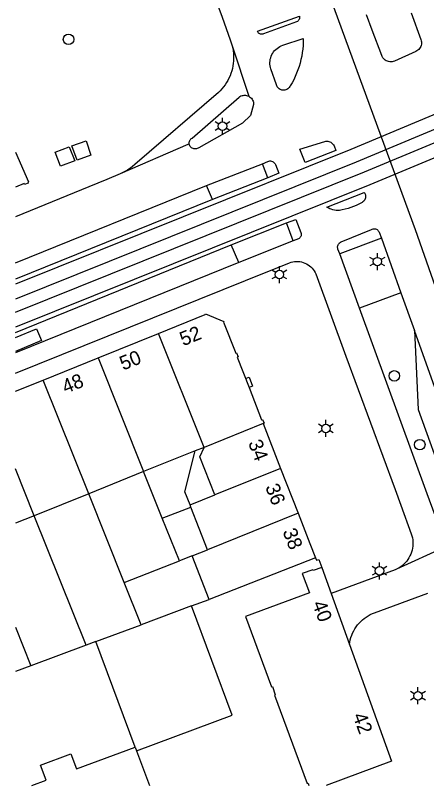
# Model space of a CAD drawing. Extents: x 122462 to 123306, y 485548 to 486417.
# Drawn here: x 122462 to 122505.6, y 485548.3 to 485629.9 of the extents above; entities that cross this region are included whole.
import ezdxf

# ---------------------------------------------------------------- set-up
doc = ezdxf.new("R2010")
doc.units = 0
for name, color, linetype in [('Level 1', 7, 'Continuous'), ('Level 17', 7, 'Continuous'), ('Level 18', 7, 'Continuous'), ('Level 19', 7, 'Continuous'), ('Level 37', 7, 'Continuous'), ('Level 4', 7, 'Continuous'), ('Level 40', 7, 'Continuous'), ('Level 42', 7, 'Continuous'), ('Level 44', 7, 'Continuous'), ('Level 50', 7, 'Continuous'), ('Level 53', 7, 'Continuous'), ('Level 58', 7, 'Continuous')]:
    doc.layers.add(name, color=color, linetype=linetype)

msp = doc.modelspace()

# ---------------------------------------------------------------- linework, layer by layer
at = {"layer": 'Level 1'}
for p, q in [((122470.791, 485593.618), (122477.188, 485596.206)), ((122464.972, 485591.263), (122470.791, 485593.618)), ((122462.03, 485590.085), (122464.972, 485591.263)), ((122488.303, 485586.662), (122490.155, 485581.91)), ((122481.105, 485583.771), (122475.629, 485581.571)), ((122482.032, 485584.143), (122481.105, 485583.771)), ((122475.629, 485581.571), (122469.807, 485579.232)), ((122490.155, 485581.91), (122492.007, 485577.158)), ((122469.807, 485579.232), (122464.019, 485576.907)), ((122480.559, 485578.056), (122483.173, 485579.106)), ((122480.65, 485577.824), (122480.559, 485578.056)), ((122482.412, 485573.304), (122480.65, 485577.824)), ((122464.019, 485576.907), (122462.03, 485576.108)), ((122480.769, 485572.644), (122482.412, 485573.304)), ((122482.568, 485568.031), (122480.769, 485572.644)), ((122494.511, 485571.416), (122495.507, 485568.664)), ((122495.507, 485568.664), (122497.456, 485563.281)), ((122480.716, 485567.344), (122482.568, 485568.031)), ((122474.726, 485552.407), (122474.878, 485551.999))]:
    msp.add_line(p, q, dxfattribs=at)
for points in [[(122462.03, 485615.407), (122463.422, 485612.251), (122463.356, 485612.224), (122463.397, 485612.117), (122463.005, 485611.965), (122462.966, 485612.068), (122462.03, 485611.693)], [(122477.188, 485596.206), (122482.171, 485598.221), (122482.199, 485598.289), (122484.13, 485597.461), (122484.102, 485597.392), (122485.398, 485594.104), (122485.489, 485594.14), (122485.651, 485593.726), (122485.559, 485593.69), (122486.808, 485590.49)], [(122486.808, 485590.49), (122488.143, 485587.071), (122488.234, 485587.107), (122488.393, 485586.695), (122488.303, 485586.662)], [(122483.173, 485579.106), (122481.6, 485583.14), (122482.032, 485584.143)], [(122492.007, 485577.158), (122493.248, 485573.974), (122493.85, 485572.428)], [(122493.85, 485572.428), (122493.947, 485572.179), (122494.199, 485572.269), (122494.511, 485571.416)], [(122474.878, 485551.999), (122485.001, 485555.779), (122480.716, 485567.344)], [(122497.456, 485563.281), (122501.929, 485550.92), (122494.98, 485548.322)], [(122463.787, 485548.322), (122465.293, 485548.884), (122464.695, 485550.486), (122467.91, 485551.687), (122468.508, 485550.086), (122474.726, 485552.407)]]:
    msp.add_lwpolyline(points, dxfattribs=at)
at = {"layer": 'Level 17'}
for p, q in [((122485.014, 485626.68), (122486.767, 485621.327)), ((122482.281, 485611.861), (122488.231, 485614.151)), ((122488.811, 485612.681), (122488.231, 485614.151)), ((122488.811, 485612.681), (122482.941, 485610.391)), ((122462.03, 485603.685), (122482.281, 485611.861)), ((122482.941, 485610.391), (122482.281, 485611.861)), ((122484.91, 485605.599), (122490.78, 485607.929)), ((122491.47, 485606.009), (122490.78, 485607.929)), ((122491.47, 485606.009), (122485.71, 485603.709)), ((122500.84, 485606.279), (122496.43, 485604.619)), ((122500.84, 485606.279), (122502.91, 485600.499)), ((122485.71, 485603.709), (122484.91, 485605.599)), ((122498.51, 485598.889), (122496.43, 485604.619)), ((122485.71, 485603.709), (122462.03, 485594.152)), ((122502.91, 485600.499), (122498.51, 485598.889)), ((122502.91, 485600.499), (122504.34, 485596.519)), ((122507.738, 485573.663), (122502.435, 485571.247))]:
    msp.add_line(p, q, dxfattribs=at)
for points in [[(122483.504, 485630.951), (122483.947, 485629.713), (122484.814, 485627.292), (122485.014, 485626.68)], [(122503.986, 485630.163), (122505.038, 485627.323), (122505.074, 485627.202), (122505.095, 485627.078), (122505.1, 485626.952), (122505.089, 485626.826), (122505.063, 485626.703), (122505.021, 485626.584), (122504.965, 485626.471), (122504.895, 485626.367), (122504.812, 485626.271), (122504.718, 485626.187), (122504.614, 485626.116), (122504.502, 485626.058), (122502.215, 485625.056), (122502.097, 485625.013), (122501.974, 485624.985), (122501.849, 485624.972), (122501.723, 485624.976), (122501.598, 485624.995), (122501.477, 485625.03), (122501.362, 485625.08), (122501.253, 485625.144), (122501.153, 485625.221), (122501.064, 485625.31), (122500.987, 485625.409), (122500.923, 485625.517), (122500.873, 485625.633), (122499.868, 485628.312), (122499.266, 485629.949)], [(122488.118, 485627.891), (122488.037, 485627.901), (122487.96, 485627.926), (122487.889, 485627.965), (122487.826, 485628.016), (122487.773, 485628.078), (122487.733, 485628.149), (122487.707, 485628.226), (122492.155, 485629.821), (122492.168, 485629.729), (122492.165, 485629.636), (122492.146, 485629.545), (122492.112, 485629.458), (122492.064, 485629.378), (122492.003, 485629.308), (122491.932, 485629.248), (122491.851, 485629.202), (122488.329, 485627.938), (122488.266, 485627.911), (122488.199, 485627.896), (122488.118, 485627.891)], [(122490.508, 485621.965), (122490.403, 485621.965), (122490.3, 485621.98), (122490.199, 485622.008), (122490.103, 485622.05), (122490.014, 485622.105), (122489.933, 485622.171), (122489.861, 485622.247), (122489.801, 485622.333), (122489.752, 485622.426), (122489.717, 485622.524), (122489.115, 485624.215), (122489.069, 485624.382), (122489.037, 485624.552), (122489.02, 485624.724), (122489.018, 485624.897), (122489.031, 485625.07), (122489.059, 485625.241), (122489.102, 485625.408), (122489.159, 485625.572), (122489.23, 485625.73), (122489.314, 485625.881), (122489.411, 485626.024), (122489.521, 485626.158), (122489.641, 485626.282), (122489.772, 485626.396), (122489.912, 485626.497), (122490.061, 485626.586), (122490.216, 485626.662), (122490.378, 485626.724), (122492.546, 485627.451), (122492.545, 485627.073), (122492.529, 485626.696), (122492.497, 485626.32), (122492.45, 485625.945), (122492.388, 485625.572), (122492.311, 485625.203), (122492.219, 485624.836), (122492.112, 485624.474), (122491.991, 485624.117), (122491.855, 485623.764), (122491.705, 485623.417), (122491.541, 485623.077), (122491.364, 485622.744), (122491.173, 485622.418), (122491.13, 485622.349), (122491.069, 485622.259), (122490.996, 485622.179), (122490.912, 485622.109), (122490.82, 485622.052), (122490.72, 485622.008), (122490.616, 485621.979), (122490.508, 485621.965)], [(122485.014, 485626.68), (122485.075, 485626.416), (122485.121, 485626.148), (122485.153, 485625.879), (122485.171, 485625.608), (122485.173, 485625.336), (122485.162, 485625.065), (122485.135, 485624.795), (122485.094, 485624.527), (122485.039, 485624.261), (122484.969, 485623.999), (122484.886, 485623.741), (122484.789, 485623.487), (122484.678, 485623.24), (122484.554, 485622.998), (122484.417, 485622.764), (122484.268, 485622.537), (122484.107, 485622.319), (122483.934, 485622.109), (122483.75, 485621.91), (122483.556, 485621.72), (122474.703, 485614.082), (122474.465, 485613.891), (122474.219, 485613.712), (122473.964, 485613.545), (122473.702, 485613.39), (122473.432, 485613.249), (122473.156, 485613.12)], [(122480.474, 485616.266), (122480.465, 485616.358), (122480.471, 485616.45), (122480.489, 485616.54), (122480.521, 485616.626), (122480.565, 485616.707), (122480.621, 485616.781), (122480.686, 485616.845), (122480.761, 485616.899), (122485.746, 485621.228), (122485.845, 485621.296), (122485.952, 485621.351), (122486.065, 485621.392), (122486.182, 485621.419), (122486.302, 485621.43), (122486.422, 485621.427), (122486.541, 485621.408), (122486.657, 485621.375), (122486.767, 485621.327)], [(122486.767, 485621.327), (122486.87, 485621.266), (122486.965, 485621.192), (122487.05, 485621.107), (122487.124, 485621.012), (122487.185, 485620.909), (122487.233, 485620.798), (122487.266, 485620.683), (122487.285, 485620.564), (122487.288, 485620.444), (122486.96, 485619.298), (122486.118, 485618.462), (122481.468, 485615.877), (122481.395, 485615.828), (122481.315, 485615.791), (122481.231, 485615.764), (122481.144, 485615.75), (122481.051, 485615.748), (122480.959, 485615.761), (122480.87, 485615.787), (122480.785, 485615.826), (122480.708, 485615.877), (122480.639, 485615.939), (122480.58, 485616.01), (122480.532, 485616.09), (122480.496, 485616.176), (122480.474, 485616.266)], [(122492.752, 485614.311), (122492.184, 485615.734), (122494.832, 485616.542), (122494.938, 485616.564), (122495.046, 485616.573), (122495.155, 485616.567), (122495.262, 485616.547), (122495.365, 485616.513), (122495.463, 485616.466), (122495.553, 485616.406), (122495.635, 485616.335), (122495.708, 485616.254), (122495.768, 485616.164), (122495.817, 485616.067), (122495.997, 485615.596), (122492.752, 485614.311)], [(122480.474, 485616.266), (122480.323, 485616.201), (122473.156, 485613.12)], [(122488.231, 485614.151), (122488.807, 485614.419), (122488.899, 485614.451), (122488.996, 485614.468), (122489.093, 485614.469), (122489.19, 485614.454), (122489.283, 485614.424), (122489.37, 485614.379), (122489.448, 485614.32), (122489.515, 485614.249), (122489.571, 485614.169), (122489.612, 485614.08), (122489.951, 485613.171), (122488.811, 485612.681)], [(122473.156, 485613.12), (122471.723, 485612.514), (122469.801, 485611.721), (122462.03, 485608.571)], [(122496.214, 485609.231), (122496.037, 485609.238), (122495.862, 485609.261), (122495.69, 485609.298), (122495.521, 485609.35), (122495.357, 485609.416), (122495.2, 485609.496), (122495.05, 485609.589), (122499.01, 485611.139), (122499.069, 485611.055), (122499.115, 485610.964), (122499.147, 485610.867), (122499.164, 485610.766), (122499.167, 485610.664), (122499.154, 485610.562), (122499.126, 485610.464), (122499.084, 485610.371), (122499.029, 485610.284), (122498.962, 485610.207), (122498.884, 485610.141), (122498.797, 485610.087), (122498.456, 485609.908), (122498.177, 485609.77), (122497.891, 485609.646), (122497.599, 485609.535), (122497.303, 485609.439), (122497.002, 485609.358), (122496.697, 485609.291), (122496.39, 485609.239), (122496.214, 485609.231)], [(122482.941, 485610.391), (122462.03, 485601.943)], [(122490.78, 485607.929), (122491.76, 485608.279), (122492.314, 485606.884), (122492.339, 485606.801), (122492.349, 485606.714), (122492.345, 485606.627), (122492.325, 485606.543), (122492.29, 485606.463), (122492.243, 485606.39), (122492.183, 485606.326), (122492.114, 485606.274), (122492.036, 485606.235), (122491.47, 485606.009)], [(122496.43, 485604.619), (122496.235, 485605.136), (122496.209, 485605.225), (122496.197, 485605.317), (122496.199, 485605.409), (122496.216, 485605.5), (122496.246, 485605.588), (122496.289, 485605.67), (122496.345, 485605.744), (122496.411, 485605.809), (122496.486, 485605.862), (122496.569, 485605.904), (122499.79, 485607.219), (122499.87, 485607.258), (122499.955, 485607.284), (122500.044, 485607.296), (122500.133, 485607.294), (122500.22, 485607.278), (122500.304, 485607.248), (122500.382, 485607.205), (122500.453, 485607.15), (122500.513, 485607.085), (122500.563, 485607.011), (122500.6, 485606.93), (122500.84, 485606.279)], [(122462.03, 485596.32), (122484.91, 485605.599)], [(122462.03, 485591.998), (122486.445, 485601.812), (122491.081, 485603.675), (122491.258, 485603.736), (122491.44, 485603.782), (122491.625, 485603.812), (122491.812, 485603.826), (122492, 485603.824), (122492.186, 485603.806), (122492.371, 485603.773), (122492.552, 485603.724), (122492.728, 485603.659), (122492.898, 485603.58), (122493.061, 485603.487), (122493.215, 485603.38), (122493.359, 485603.26), (122493.493, 485603.128), (122493.615, 485602.986), (122493.724, 485602.834), (122493.82, 485602.673), (122493.902, 485602.504), (122497.08, 485593.799), (122502.289, 485579.69), (122502.894, 485578.034), (122504.014, 485574.968), (122504.077, 485574.761), (122504.125, 485574.549), (122504.158, 485574.335), (122504.176, 485574.119), (122504.178, 485573.902), (122504.164, 485573.685), (122504.135, 485573.471), (122504.091, 485573.258), (122504.032, 485573.05), (122503.958, 485572.846), (122503.869, 485572.648), (122503.767, 485572.457), (122503.651, 485572.274), (122503.522, 485572.099), (122503.381, 485571.934), (122503.229, 485571.78), (122503.066, 485571.637), (122502.894, 485571.505), (122502.712, 485571.387), (122502.435, 485571.247)], [(122507.738, 485573.663), (122505.706, 485579.217), (122498.51, 485598.889)], [(122521.644, 485548.322), (122509.916, 485580.988), (122504.34, 485596.519)], [(122504.34, 485596.519), (122504.742, 485588.142), (122507.678, 485580.047), (122509.348, 485575.418), (122509.376, 485575.322), (122509.392, 485575.223), (122509.395, 485575.123), (122509.386, 485575.024), (122509.364, 485574.926), (122509.331, 485574.832), (122509.095, 485574.31), (122509.038, 485574.218), (122508.969, 485574.135), (122508.888, 485574.063), (122508.797, 485574.004), (122508.699, 485573.959), (122507.738, 485573.663)], [(122502.435, 485571.247), (122502.292, 485571.185), (122495.507, 485568.664)], [(122497.456, 485563.281), (122497.493, 485563.528), (122497.545, 485563.773), (122497.612, 485564.013), (122497.694, 485564.249), (122497.79, 485564.48), (122497.9, 485564.704), (122498.023, 485564.922), (122498.16, 485565.131), (122498.31, 485565.331), (122498.471, 485565.522), (122498.644, 485565.702), (122498.827, 485565.872), (122499.021, 485566.029), (122499.224, 485566.175), (122499.436, 485566.308), (122499.655, 485566.427), (122499.882, 485566.533), (122500.114, 485566.625), (122505.771, 485568.706)]]:
    msp.add_lwpolyline(points, dxfattribs=at)
at = {"layer": 'Level 18'}
msp.add_lwpolyline([(122462.03, 485722.381), (122475.9, 485684.915), (122504.434, 485607.215), (122525.107, 485548.322)], dxfattribs=at)
at = {"layer": 'Level 19'}
for p, q in [((122477.61, 485576.638), (122475.629, 485581.571)), ((122473.58, 485569.84), (122469.807, 485579.232)), ((122477.61, 485576.638), (122480.65, 485577.824)), ((122469.528, 485563.19), (122464.019, 485576.907)), ((122479.425, 485572.12), (122477.61, 485576.638)), ((122480.769, 485572.644), (122479.425, 485572.12)), ((122473.58, 485569.84), (122479.425, 485572.12)), ((122475.379, 485565.362), (122473.58, 485569.84)), ((122480.716, 485567.344), (122475.379, 485565.362)), ((122462.03, 485565.116), (122463.676, 485561.018)), ((122470.558, 485563.572), (122475.379, 485565.362)), ((122470.558, 485563.572), (122469.528, 485563.19)), ((122474.726, 485552.407), (122470.558, 485563.572)), ((122469.528, 485563.19), (122463.676, 485561.018)), ((122463.676, 485561.018), (122462.03, 485560.407))]:
    msp.add_line(p, q, dxfattribs=at)
msp.add_lwpolyline([(122480.559, 485578.056), (122480.005, 485579.436), (122481.105, 485583.771)], dxfattribs=at)
at = {"layer": 'Level 37'}
for points in [[(122831.695, 485753.286), (122749.349, 485719.414), (122746.888, 485718.394), (122744.433, 485717.362), (122741.982, 485716.318), (122739.537, 485715.262), (122737.097, 485714.193), (122734.663, 485713.112), (122732.234, 485712.019), (122729.811, 485710.913), (122727.393, 485709.796), (122725.051, 485708.714), (122722.702, 485707.646), (122720.348, 485706.592), (122717.987, 485705.55), (122715.621, 485704.523), (122713.249, 485703.509), (122710.871, 485702.509), (122708.487, 485701.522), (122706.098, 485700.549), (122540.465, 485633.647), (122497.591, 485615.701), (122462.03, 485601.437)], [(122832.259, 485751.918), (122749.912, 485718.045), (122747.458, 485717.028), (122745.009, 485715.999), (122742.566, 485714.958), (122740.128, 485713.905), (122737.695, 485712.839), (122735.267, 485711.761), (122732.845, 485710.671), (122730.428, 485709.568), (122728.017, 485708.454), (122725.667, 485707.369), (122723.311, 485706.297), (122720.949, 485705.239), (122718.581, 485704.195), (122716.207, 485703.164), (122713.827, 485702.146), (122711.441, 485701.143), (122709.049, 485700.153), (122706.652, 485699.177), (122541.028, 485632.278), (122498.152, 485614.332), (122462.03, 485599.841)], [(122462.03, 485598.45), (122499.057, 485613.321), (122548.623, 485633.976), (122706.621, 485697.803), (122708.996, 485698.77), (122711.365, 485699.751), (122713.729, 485700.746), (122716.087, 485701.753), (122718.44, 485702.774), (122720.787, 485703.808), (122723.127, 485704.856), (122725.462, 485705.916), (122727.791, 485706.99), (122730.21, 485708.107), (122732.634, 485709.211), (122735.064, 485710.304), (122737.499, 485711.384), (122739.94, 485712.452), (122742.386, 485713.508), (122744.837, 485714.552), (122747.294, 485715.584), (122749.755, 485716.603), (122832.9, 485750.796)], [(122833.463, 485749.428), (122750.317, 485715.234), (122747.862, 485714.217), (122745.413, 485713.189), (122742.969, 485712.148), (122740.53, 485711.095), (122738.096, 485710.029), (122735.667, 485708.952), (122733.244, 485707.863), (122730.827, 485706.761), (122728.414, 485705.648), (122726.078, 485704.571), (122723.735, 485703.506), (122721.387, 485702.455), (122719.033, 485701.418), (122716.672, 485700.394), (122714.306, 485699.383), (122711.935, 485698.385), (122709.557, 485697.401), (122707.175, 485696.431), (122549.185, 485632.607), (122499.617, 485611.951), (122462.03, 485596.856)]]:
    msp.add_lwpolyline(points, dxfattribs=at)
at = {"layer": 'Level 4'}
for p, q in [((122482.032, 485584.143), (122477.188, 485596.206)), ((122470.791, 485593.618), (122475.629, 485581.571)), ((122469.807, 485579.232), (122464.972, 485591.263)), ((122488.303, 485586.662), (122482.032, 485584.143)), ((122464.019, 485576.907), (122462.03, 485581.857)), ((122490.155, 485581.91), (122483.173, 485579.106)), ((122492.007, 485577.158), (122482.412, 485573.304)), ((122493.85, 485572.428), (122482.568, 485568.031)), ((122474.878, 485551.999), (122476.251, 485548.322))]:
    msp.add_line(p, q, dxfattribs=at)
msp.add_lwpolyline([(122494.511, 485571.416), (122493.618, 485571.094), (122493.583, 485571.188), (122492.456, 485570.781), (122493.214, 485568.729), (122486.424, 485566.213), (122489.182, 485558.768), (122489.276, 485558.803), (122489.592, 485557.949), (122489.498, 485557.914), (122492.973, 485548.537), (122493.067, 485548.572), (122493.16, 485548.322)], dxfattribs=at)
at = {"layer": 'Level 40'}
msp.add_lwpolyline([(122486.445, 485591.422), (122486.815, 485591.566), (122487.179, 485590.635), (122486.808, 485590.49)], dxfattribs=at)
at = {"layer": 'Level 42'}
for points in [[(122468.565, 485614.546), (122468.019, 485616.077), (122469.527, 485616.597), (122470.043, 485615.089), (122468.565, 485614.546)], [(122466.818, 485613.924), (122466.239, 485615.414), (122467.746, 485615.978), (122468.325, 485614.488), (122466.818, 485613.924)]]:
    msp.add_lwpolyline(points, dxfattribs=at)
at = {"layer": 'Level 44'}
msp.add_lwpolyline([(122462.03, 485595.77), (122464.267, 485596.708), (122464.79, 485595.459), (122462.03, 485594.301)], dxfattribs=at)
at = {"layer": 'Level 50'}
for p, q in [((122483.998, 485618.603), (122483.998, 485619.053)), ((122483.608, 485618.378), (122483.218, 485618.603)), ((122483.608, 485617.928), (122483.218, 485617.703)), ((122484.777, 485618.603), (122484.387, 485618.378)), ((122484.777, 485617.703), (122484.387, 485617.928)), ((122483.998, 485617.253), (122483.998, 485617.703)), ((122500.02, 485604.034), (122499.63, 485604.259)), ((122500.41, 485604.259), (122500.41, 485604.709)), ((122501.189, 485604.259), (122500.799, 485604.034)), ((122490.02, 485602.889), (122490.02, 485603.339)), ((122500.02, 485603.584), (122499.63, 485603.359)), ((122500.41, 485602.909), (122500.41, 485603.359)), ((122501.189, 485603.359), (122500.799, 485603.584)), ((122489.63, 485602.664), (122489.24, 485602.889)), ((122490.799, 485602.889), (122490.409, 485602.664)), ((122489.63, 485602.214), (122489.24, 485601.989)), ((122490.02, 485601.539), (122490.02, 485601.989)), ((122490.799, 485601.989), (122490.409, 485602.214)), ((122494.96, 485586.589), (122494.96, 485587.039)), ((122494.57, 485586.364), (122494.18, 485586.589)), ((122495.739, 485586.589), (122495.349, 485586.364)), ((122494.57, 485585.914), (122494.18, 485585.689)), ((122494.96, 485585.239), (122494.96, 485585.689)), ((122495.739, 485585.689), (122495.349, 485585.914)), ((122500.25, 485571.284), (122499.86, 485571.509)), ((122500.64, 485571.509), (122500.64, 485571.959)), ((122501.419, 485571.509), (122501.029, 485571.284)), ((122500.25, 485570.834), (122499.86, 485570.609)), ((122501.419, 485570.609), (122501.029, 485570.834)), ((122500.64, 485570.159), (122500.64, 485570.609)), ((122504.72, 485558.279), (122504.72, 485558.729)), ((122504.33, 485558.054), (122503.94, 485558.279)), ((122504.33, 485557.604), (122503.94, 485557.379)), ((122505.499, 485558.279), (122505.109, 485558.054)), ((122505.499, 485557.379), (122505.109, 485557.604)), ((122504.72, 485556.929), (122504.72, 485557.379))]:
    msp.add_line(p, q, dxfattribs=at)
for centre in [(122483.998, 485618.153), (122500.41, 485603.809), (122490.02, 485602.439), (122494.96, 485586.139), (122500.64, 485571.059), (122504.72, 485557.829)]:
    msp.add_circle(centre, 0.45, dxfattribs=at)
at = {"layer": 'Level 53'}
for centre in [(122467.67, 485627.349), (122502.21, 485591.709), (122504.91, 485584.429)]:
    msp.add_circle(centre, 0.56, dxfattribs=at)

# ---------------------------------------------------------------- texts
at = {"layer": 'Level 58'}
for s, rotation, p in [('52', 21.89513, (122479.823, 485594.843)), ('50', 21.89513, (122473.45, 485592.267)), ('48', 21.89513, (122467.342, 485589.797)), ('34', 291.29352, (122486.686, 485584.619)), ('36', 291.29335, (122488.504, 485579.955)), ('38', 291.30658, (122490.34, 485575.242)), ('40', 290.32046, (122493.487, 485567.598)), ('42', 290.33662, (122497.771, 485555.728))]:
    msp.add_text(s, height=1.5, rotation=rotation, dxfattribs=at).set_placement(p)

doc.saveas('drawing.dxf')
